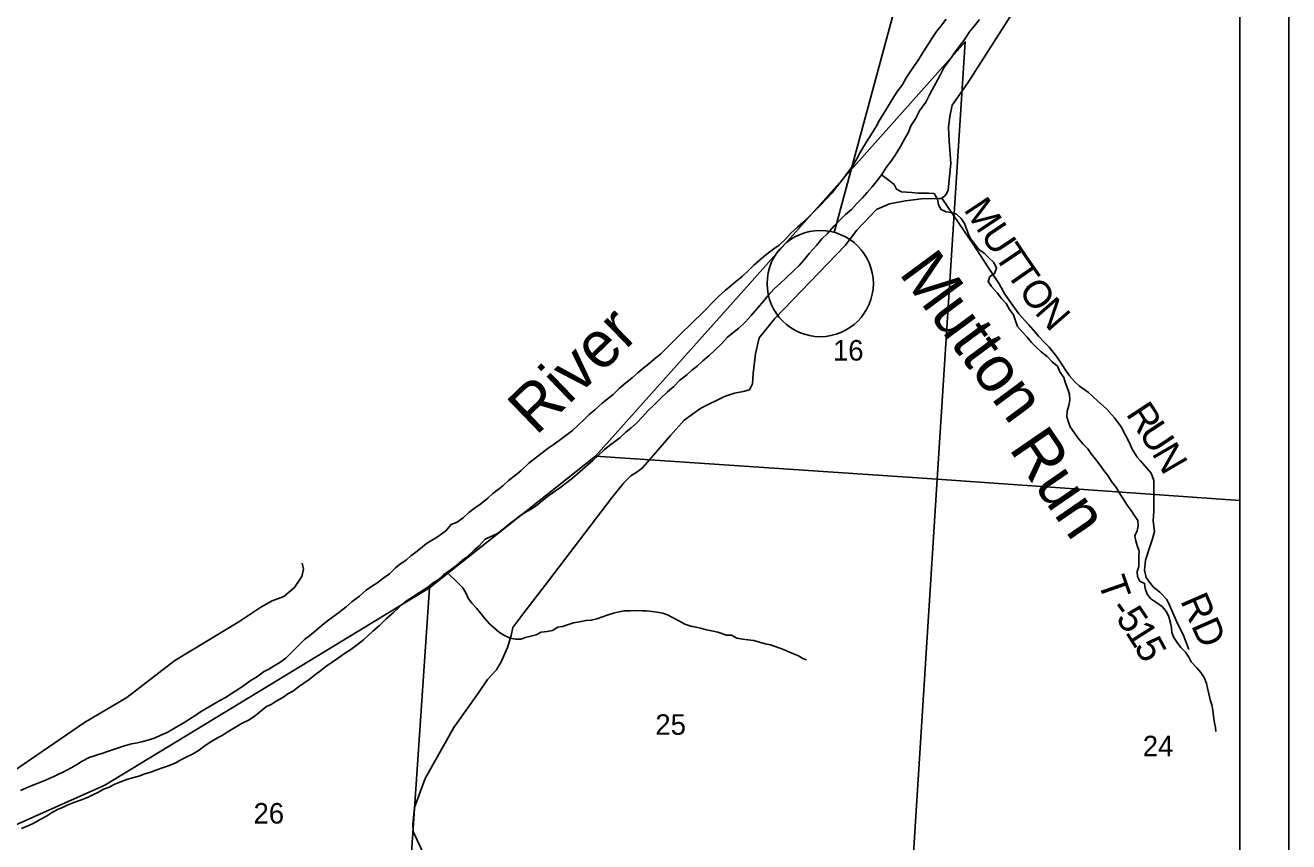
# Model space of a CAD drawing. Extents: x 0 to 34, y 0 to 22.
# Drawn here: x 28.342 to 30.917, y 18.211 to 19.875 of the extents above; entities that cross this region are included whole.
import ezdxf

# ---------------------------------------------------------------- set-up
doc = ezdxf.new("R2010")
doc.units = 0
for name, color, linetype in [('GM_X_County', 7, 'Continuous'), ('GM_X_County_Road', 7, 'Continuous'), ('GM_X_Major_River', 7, 'Continuous'), ('GM_X_Major_River_Text', 7, 'Continuous'), ('GM_X_Minor_River', 7, 'Continuous'), ('GM_X_Minor_River_Text', 7, 'Continuous'), ('GM_X_Section', 7, 'Continuous'), ('GM_X_Section_Text', 7, 'Continuous'), ('GM_X_Township', 7, 'Continuous'), ('GM_X_Township_Road', 7, 'Continuous'), ('GM_X_Township_Road_Text', 7, 'Continuous'), ('SH_Data', 7, 'Continuous'), ('SH_Text', 7, 'Continuous')]:
    doc.layers.add(name, color=color, linetype=linetype)

msp = doc.modelspace()

# ---------------------------------------------------------------- linework, layer by layer
at = {"layer": 'GM_X_County'}
msp.add_lwpolyline([(24.0167, 20.4902), (24.0167, 14.1), (30.8167, 14.1), (30.8167, 19.9966)], dxfattribs=at)
at = {"layer": 'GM_X_County_Road'}
msp.add_lwpolyline([(29.1552, 18.1847), (29.1406, 18.2141), (29.1328, 18.2316), (29.1317, 18.2467), (29.135, 18.2805), (29.1569, 18.3396), (29.2155, 18.444), (29.2659, 18.5147), (29.2838, 18.5419), (29.3021, 18.5615), (29.3121, 18.5778), (29.3244, 18.6066), (29.3321, 18.6316), (29.3356, 18.6479), (29.3562, 18.6747), (29.4085, 18.7427), (29.5364, 18.9113), (29.5616, 18.9422), (29.576, 18.9566), (29.5913, 18.9664), (29.6008, 18.9739), (29.6568, 19.0385), (29.685, 19.0702), (29.7185, 19.0947), (29.7668, 19.1183), (29.7876, 19.125), (29.8051, 19.1287), (29.8176, 19.1317), (29.8241, 19.1442), (29.825, 19.1654), (29.8302, 19.2053), (29.8376, 19.2375), (29.8692, 19.2771), (30.0126, 19.4263), (30.0366, 19.4573), (30.0622, 19.4844), (30.0763, 19.4996), (30.1029, 19.5112), (30.1355, 19.5171), (30.1681, 19.521), (30.2053, 19.5217), (30.2083, 19.5219), (30.2097, 19.5223), (30.2151, 19.5265), (30.2196, 19.5314), (30.2227, 19.5386), (30.2284, 19.594), (30.2245, 19.6384), (30.2235, 19.6661), (30.2259, 19.6885), (30.2306, 19.7117), (30.2627, 19.7574), (30.358, 19.9065)], dxfattribs=at)
at = {"layer": 'GM_X_Major_River'}
for points in [[(30.2186, 19.8869), (30.2075, 19.873), (30.1991, 19.8617), (30.1906, 19.8496), (30.1825, 19.8372), (30.1748, 19.8251), (30.1682, 19.8142), (30.1609, 19.8025), (30.1544, 19.7927), (30.1455, 19.7795), (30.1371, 19.7678), (30.1297, 19.7543), (30.1182, 19.7381), (30.1086, 19.7234), (30.0986, 19.7064), (30.0909, 19.6943), (30.0828, 19.6812), (30.0758, 19.6687), (30.0658, 19.6521), (30.0565, 19.637), (30.05, 19.6269), (30.0442, 19.6171), (30.0373, 19.6042), (30.0288, 19.5899), (30.0219, 19.5798), (30.0138, 19.5685), (30.0061, 19.5583), (29.9938, 19.5432), (29.9862, 19.5335), (29.9739, 19.5203), (29.9632, 19.5087), (29.9509, 19.4963), (29.9394, 19.4854), (29.9268, 19.473), (29.9157, 19.4633), (29.9023, 19.4509), (29.8916, 19.4396), (29.8786, 19.4268), (29.8672, 19.4194), (29.8569, 19.4119), (29.8462, 19.4029), (29.8366, 19.3947), (29.8263, 19.3853), (29.8156, 19.3748), (29.803, 19.3628), (29.7896, 19.3519), (29.7797, 19.3436), (29.7682, 19.3343), (29.7548, 19.3223), (29.7407, 19.308), (29.7318, 19.2982), (29.7181, 19.2847), (29.7058, 19.2731), (29.6947, 19.2626), (29.6836, 19.2517), (29.6637, 19.2314), (29.6496, 19.2172), (29.637, 19.2055), (29.6236, 19.1943), (29.6129, 19.1849), (29.6007, 19.1752), (29.59, 19.1662), (29.5785, 19.1565), (29.5659, 19.146), (29.5525, 19.1347), (29.5399, 19.1223), (29.5304, 19.1149), (29.5174, 19.1044), (29.5028, 19.0912), (29.4914, 19.0815), (29.4811, 19.0717), (29.4681, 19.0594), (29.4573, 19.0492), (29.4436, 19.0388), (29.4299, 19.0286), (29.418, 19.02), (29.4077, 19.0129), (29.3955, 19.0036), (29.3841, 18.995), (29.368, 18.9823), (29.3524, 18.9676), (29.3409, 18.9583), (29.3268, 18.947), (29.3153, 18.9361), (29.3054, 18.929), (29.2947, 18.9204), (29.2844, 18.9114), (29.2706, 18.8998), (29.2592, 18.892)], [(29.3045, 18.8388), (29.319, 18.8508), (29.3297, 18.8598), (29.3396, 18.8673), (29.3499, 18.8751), (29.3652, 18.8849), (29.377, 18.8916), (29.3865, 18.8983), (29.3961, 18.9062), (29.409, 18.9163), (29.4228, 18.926), (29.4331, 18.9338), (29.4453, 18.9432), (29.4571, 18.9522), (29.4671, 18.9604), (29.4774, 18.9694), (29.4881, 18.9792), (29.4984, 18.9882), (29.5095, 18.9983), (29.5217, 19.0099), (29.5324, 19.0185), (29.5427, 19.0256), (29.5534, 19.0343), (29.566, 19.0455), (29.5763, 19.0537), (29.5874, 19.0639), (29.6001, 19.077), (29.6108, 19.089), (29.6226, 19.1007), (29.6356, 19.1138), (29.6509, 19.1281), (29.6636, 19.1389), (29.6762, 19.1517), (29.6903, 19.1622), (29.7006, 19.1719), (29.7109, 19.1798), (29.7228, 19.191), (29.7354, 19.2015), (29.7465, 19.212), (29.7599, 19.2252), (29.7729, 19.2391), (29.784, 19.2477), (29.7962, 19.2578), (29.8088, 19.2698), (29.8211, 19.2833), (29.8341, 19.298), (29.8468, 19.3134), (29.8552, 19.3232), (29.8682, 19.3375), (29.8808, 19.3491), (29.8927, 19.3604), (29.9061, 19.3727), (29.9191, 19.3855), (29.9287, 19.396), (29.9394, 19.4099), (29.9547, 19.4257), (29.9651, 19.4393), (29.977, 19.4505), (29.9904, 19.4663), (30.0015, 19.4768), (30.0133, 19.4888), (30.026, 19.4993), (30.0367, 19.5114), (30.0478, 19.523), (30.0574, 19.5339), (30.0677, 19.5456), (30.0788, 19.5591), (30.0873, 19.5708), (30.0965, 19.5847), (30.1077, 19.6001), (30.115, 19.6103), (30.1258, 19.6276), (30.1347, 19.6442), (30.1416, 19.6571), (30.1467, 19.6695), (30.1559, 19.6842), (30.1644, 19.7001), (30.1771, 19.7178), (30.1848, 19.7332), (30.1902, 19.7434), (30.1976, 19.7566), (30.2061, 19.7732), (30.2138, 19.7879), (30.223, 19.8004), (30.23, 19.8102), (30.2369, 19.8207), (30.245, 19.8312), (30.2569, 19.8463), (30.2657, 19.861), (30.2757, 19.8727), (30.2864, 19.8862)], [(29.2592, 18.892), (29.2462, 18.8819), (29.2343, 18.871), (29.2221, 18.862), (29.2096, 18.8576), (29.1988, 18.8448), (29.1843, 18.834), (29.1733, 18.8269), (29.1596, 18.8187), (29.1477, 18.8089), (29.1382, 18.8014), (29.1279, 18.7939), (29.1179, 18.7846), (29.1073, 18.7779), (29.0966, 18.7689), (29.084, 18.7569), (29.0706, 18.7471), (29.0607, 18.7396), (29.0473, 18.7311), (29.037, 18.7236), (29.0229, 18.7116), (29.0076, 18.6996), (28.9962, 18.6899), (28.9839, 18.6801), (28.9572, 18.6607), (28.9477, 18.6532), (28.9332, 18.6408), (28.9209, 18.6303), (28.911, 18.6229), (28.8965, 18.609), (28.885, 18.597), (28.8728, 18.5853), (28.8606, 18.5764), (28.8495, 18.5696), (28.8381, 18.5629), (28.8278, 18.557), (28.8152, 18.548), (28.8003, 18.5387), (28.7896, 18.5308), (28.7744, 18.5207), (28.7622, 18.5133), (28.7511, 18.5058), (28.7386, 18.4991), (28.7233, 18.4898), (28.7104, 18.4823), (28.6993, 18.4756), (28.6894, 18.4689), (28.6764, 18.461), (28.6635, 18.4525), (28.6463, 18.4428), (28.6311, 18.4338), (28.6182, 18.4279), (28.6068, 18.4231), (28.5946, 18.4186), (28.5817, 18.4154), (28.5707, 18.4128), (28.5585, 18.4103), (28.5441, 18.4063), (28.5338, 18.4029), (28.5198, 18.3985), (28.5099, 18.3952), (28.5004, 18.3915)], [(28.4915, 18.3124), (28.5015, 18.3183), (28.5114, 18.3217), (28.5247, 18.3284), (28.535, 18.3324), (28.5487, 18.3376), (28.5605, 18.3413), (28.5734, 18.3449), (28.5859, 18.3494), (28.5981, 18.3526), (28.6103, 18.3575), (28.6217, 18.3615), (28.6338, 18.3656), (28.6487, 18.3715), (28.6593, 18.3778), (28.6715, 18.3838), (28.6829, 18.3897), (28.6963, 18.3979), (28.7089, 18.4069), (28.7199, 18.4144), (28.7336, 18.4229), (28.7432, 18.4278), (28.7535, 18.4345), (28.7668, 18.4427), (28.7843, 18.4524), (28.7969, 18.4591), (28.8102, 18.4677), (28.8224, 18.4778), (28.8335, 18.4864), (28.843, 18.4905), (28.8533, 18.4972), (28.8667, 18.505), (28.8773, 18.5125), (28.8884, 18.5185), (28.8991, 18.5267), (28.9204, 18.5416), (28.9338, 18.5525), (28.9445, 18.56), (28.9548, 18.5678), (28.9674, 18.5768), (28.9781, 18.5847), (28.9926, 18.5948), (29.0055, 18.603), (29.0193, 18.6131), (29.0311, 18.6224), (29.041, 18.631), (29.0506, 18.6404), (29.064, 18.6517), (29.0777, 18.6652), (29.0922, 18.6779), (29.1049, 18.6895), (29.1144, 18.6986), (29.1255, 18.706), (29.14, 18.7157), (29.1506, 18.7221), (29.1625, 18.7295), (29.1735, 18.7389), (29.1842, 18.7456), (29.1945, 18.7546), (29.2079, 18.7643), (29.2193, 18.773), (29.232, 18.7846), (29.2419, 18.7909), (29.2575, 18.8059), (29.2671, 18.8142), (29.2794, 18.8277), (29.3045, 18.8388)], [(28.5004, 18.3915), (28.4722, 18.3827), (28.4581, 18.3749), (28.4486, 18.3693), (28.4368, 18.3623), (28.4265, 18.3571), (28.3999, 18.3441), (28.3832, 18.3363), (28.3714, 18.3315), (28.3577, 18.326), (28.3433, 18.3201), (28.3326, 18.3157)], [(28.3341, 18.2379), (28.3462, 18.2427), (28.358, 18.2483), (28.3725, 18.2561), (28.3854, 18.2631), (28.3957, 18.2702), (28.4075, 18.2765), (28.4181, 18.2806), (28.4276, 18.2858), (28.4409, 18.2913), (28.4546, 18.2961), (28.4687, 18.3012), (28.4797, 18.3064), (28.4915, 18.3124)]]:
    msp.add_lwpolyline(points, dxfattribs=at)
at = {"layer": 'GM_X_Minor_River'}
for points in [[(30.0867, 19.5699), (30.1024, 19.5581), (30.1125, 19.5503), (30.1172, 19.5407), (30.1277, 19.5355), (30.1379, 19.5345), (30.1489, 19.5343), (30.1613, 19.5329), (30.1715, 19.5323), (30.1825, 19.5328), (30.1939, 19.5322), (30.2012, 19.5202), (30.2032, 19.5088), (30.2083, 19.4992), (30.2184, 19.4944), (30.229, 19.4931), (30.2395, 19.4898), (30.2495, 19.4812), (30.2557, 19.4705), (30.2597, 19.4601), (30.264, 19.4494), (30.269, 19.4391), (30.2768, 19.4287), (30.2852, 19.4175), (30.2957, 19.4104), (30.3053, 19.4007), (30.3157, 19.3914), (30.3211, 19.3795), (30.3174, 19.3686), (30.3078, 19.3627), (30.3042, 19.3526), (30.3108, 19.3422), (30.3226, 19.3294), (30.3311, 19.3182), (30.3411, 19.3077), (30.3476, 19.2958), (30.3557, 19.285), (30.3589, 19.2743), (30.3639, 19.2609), (30.375, 19.2489), (30.3838, 19.2393), (30.3927, 19.2281), (30.4023, 19.2191), (30.4119, 19.2094), (30.4242, 19.2), (30.4346, 19.1892), (30.4457, 19.1798), (30.4504, 19.1687), (30.4585, 19.1568), (30.4616, 19.1454), (30.4667, 19.1331), (30.4702, 19.1228), (30.4703, 19.1106), (30.4689, 19.0997), (30.4653, 19.0884), (30.4646, 19.0766), (30.4678, 19.0663), (30.4714, 19.0564), (30.4794, 19.0452), (30.4871, 19.034), (30.4975, 19.0213), (30.5071, 19.0116), (30.5144, 19.0016), (30.5229, 18.9907), (30.5317, 18.9792), (30.5398, 18.9672), (30.5479, 18.9572), (30.5556, 18.9453), (30.5659, 18.9321), (30.5721, 18.921), (30.5794, 18.9098), (30.5875, 18.8971), (30.5959, 18.886), (30.6018, 18.8763), (30.6095, 18.8655), (30.61, 18.8545), (30.6075, 18.8443), (30.6031, 18.8342), (30.6048, 18.8243), (30.6076, 18.8144), (30.6122, 18.8033), (30.6113, 18.7931), (30.611, 18.7828), (30.6112, 18.7718), (30.6079, 18.7616), (30.6084, 18.7518), (30.6131, 18.7422), (30.6229, 18.7374), (30.6242, 18.7271), (30.6281, 18.7157), (30.6358, 18.706), (30.6459, 18.6994), (30.6597, 18.6896), (30.6674, 18.6792), (30.6725, 18.6696), (30.676, 18.657), (30.6777, 18.6467), (30.6786, 18.6372), (30.6825, 18.6269), (30.6891, 18.6168), (30.6965, 18.6068)], [(29.2019, 18.7599), (29.2231, 18.7393), (29.2338, 18.7284), (29.2397, 18.7184), (29.2447, 18.7073), (29.2521, 18.6969), (29.2613, 18.6868), (29.2705, 18.6764), (29.2783, 18.6656), (29.2883, 18.6551), (29.2979, 18.6462), (29.3087, 18.6372), (29.3184, 18.6313), (29.33, 18.6258), (29.3413, 18.6236), (29.3519, 18.6241), (29.3615, 18.627), (29.3721, 18.6298), (29.3828, 18.6329), (29.3932, 18.638), (29.4053, 18.6393), (29.4163, 18.6417), (29.4271, 18.6483), (29.4366, 18.6499), (29.4469, 18.6531), (29.4591, 18.657), (29.4717, 18.6594), (29.485, 18.6621), (29.4952, 18.6623), (29.5066, 18.6655), (29.5185, 18.669), (29.5295, 18.6733), (29.541, 18.6768), (29.552, 18.6792), (29.5627, 18.6813), (29.574, 18.6818), (29.585, 18.6819), (29.5987, 18.6816), (29.6081, 18.6818), (29.6194, 18.68), (29.6296, 18.679), (29.641, 18.6765), (29.6507, 18.6733), (29.6612, 18.6681), (29.6754, 18.6602), (29.6863, 18.6546), (29.6983, 18.6506), (29.7089, 18.6481), (29.7206, 18.6455), (29.7303, 18.6427), (29.7405, 18.6405), (29.753, 18.638), (29.771, 18.6319), (29.7812, 18.6321), (29.7921, 18.6261), (29.8045, 18.6236), (29.8147, 18.6222), (29.8264, 18.6208), (29.8385, 18.6175), (29.8498, 18.6146), (29.8603, 18.6121), (29.8701, 18.6092), (29.8817, 18.6048), (29.8922, 18.6008), (29.9039, 18.5952), (29.9163, 18.5907), (29.9263, 18.5841), (29.9339, 18.5816)], [(30.6965, 18.6068), (30.7061, 18.5975), (30.7134, 18.5871), (30.7181, 18.5775), (30.7285, 18.5663), (30.7377, 18.5558), (30.7443, 18.5455), (30.749, 18.5332), (30.751, 18.5237), (30.7538, 18.5126), (30.7569, 18.5), (30.7597, 18.4901), (30.7618, 18.4791), (30.7634, 18.4669), (30.7653, 18.4532), (30.7674, 18.4437), (30.7684, 18.4357)]]:
    msp.add_lwpolyline(points, dxfattribs=at)
at = {"layer": 'GM_X_Section'}
msp.add_line((30.8167, 17.9065), (30.8167, 18.9061), dxfattribs=at)
for points in [[(29.7952, 19.323), (30.2571, 19.8411), (30.2006, 18.9496), (29.5042, 18.9967)], [(29.5042, 18.9967), (30.2006, 18.9496), (30.1374, 17.9516), (29.1178, 18.0184), (29.1658, 18.7281)], [(29.1658, 18.7281), (29.1178, 18.0184), (28.5033, 18.0906), (28.5064, 18.0521), (28.157, 18.0791), (28.1647, 18.1688), (28.1804, 18.1807), (28.214, 18.1975), (28.5041, 18.3264), (28.8554, 18.5398)]]:
    msp.add_lwpolyline(points, close=True, dxfattribs=at)
msp.add_lwpolyline([(30.8167, 18.9061), (30.2006, 18.9496), (30.1374, 17.9516), (30.8167, 17.9065)], dxfattribs=at)
at = {"layer": 'GM_X_Township'}
msp.add_lwpolyline([(27.704, 14.1), (30.8167, 14.1), (30.8167, 19.9966)], dxfattribs=at)
at = {"layer": 'GM_X_Township_Road'}
for points in [[(30.7133, 18.6028), (30.7013, 18.6332), (30.6897, 18.6557), (30.6826, 18.6724), (30.6737, 18.693), (30.6681, 18.7047), (30.6538, 18.7193), (30.6402, 18.7303), (30.6349, 18.7372), (30.6259, 18.7494), (30.6226, 18.7642), (30.6246, 18.7851), (30.6327, 18.8101), (30.6389, 18.8283), (30.6431, 18.8431), (30.6402, 18.8658), (30.6419, 18.8848), (30.642, 18.9061), (30.6417, 18.9205), (30.6418, 18.9345), (30.6419, 18.9474), (30.6363, 18.9619), (30.6148, 18.9875), (30.6081, 18.9947), (30.5975, 19.0107), (30.5919, 19.0236), (30.5751, 19.0564), (30.5616, 19.0747), (30.5458, 19.0926), (30.5269, 19.1094), (30.5085, 19.1266), (30.4904, 19.1396), (30.4809, 19.1484), (30.4697, 19.1606), (30.4614, 19.1736), (30.4516, 19.188), (30.4423, 19.2021), (30.4287, 19.2185), (30.4193, 19.2285), (30.4065, 19.2411), (30.396, 19.254), (30.3866, 19.2651), (30.367, 19.2865), (30.3509, 19.3086), (30.3381, 19.3265), (30.3265, 19.3482), (30.3032, 19.3825), (30.2736, 19.4286), (30.2341, 19.4865), (30.2097, 19.5223)], [(27.1485, 18.1572), (27.153, 18.1629), (27.1629, 18.1674), (27.1753, 18.1651), (27.1953, 18.1509), (27.2498, 18.1328), (27.436, 18.1203), (27.6307, 18.1188), (27.944, 18.1227), (27.9625, 18.1237), (27.9982, 18.1364), (28.4629, 18.4537), (28.5488, 18.5052), (28.6466, 18.5805), (28.777, 18.6591), (28.8222, 18.6888), (28.8454, 18.7016), (28.8686, 18.7105), (28.8906, 18.7294), (28.9056, 18.7513), (28.9087, 18.7665), (28.9065, 18.7786)]]:
    msp.add_lwpolyline(points, dxfattribs=at)
at = {"layer": 'SH_Data'}
for points in [[(23.9167, 21), (30.9167, 21), (30.9167, 14), (23.9167, 14)], [(24.0167, 20.9), (30.8167, 20.9), (30.8167, 14.1), (24.0167, 14.1)]]:
    msp.add_lwpolyline(points, close=True, dxfattribs=at)
at = {"layer": 'SH_Text'}
msp.add_line((29.9902, 19.4527), (30.4732, 21.2354), dxfattribs=at)
msp.add_circle((29.962, 19.3483), 0.1082, dxfattribs=at)

# ---------------------------------------------------------------- texts
at = {"layer": 'GM_X_Major_River_Text'}
msp.add_text('River', height=0.09471, rotation=43.9767, dxfattribs=at).set_placement((29.3829, 19.037))
at = {"layer": 'GM_X_Minor_River_Text'}
for s, height, rotation, p in [('Mutton', 0.0947, 306.477, (30.121, 19.3693)), ('Run', 0.09471, 304.4804, (30.3451, 19.0121))]:
    msp.add_text(s, height=height, rotation=rotation, dxfattribs=at).set_placement(p)
at = {"layer": 'GM_X_Section_Text'}
for s, p in [('16', (29.988, 19.1915)), ('25', (29.626, 18.429)), ('24', (30.6193, 18.3851)), ('26', (28.8072, 18.2481))]:
    msp.add_text(s, height=0.04186, rotation=0, dxfattribs=at).set_placement(p)
at = {"layer": 'GM_X_Township_Road_Text'}
for s, height, rotation, p in [('M', 0.0568, 303.5328, (30.2531, 19.4992)), ('U', 0.0568, 303.5372, (30.2872, 19.4478)), ('T', 0.0568, 303.8085, (30.315, 19.4058)), ('T', 0.0568, 304.9313, (30.3393, 19.3695)), ('O', 0.0568, 306.0268, (30.3643, 19.3337)), ('N', 0.0568, 311.1718, (30.3972, 19.2889)), ('R', 0.0568, 303.3848, (30.5838, 19.0827)), ('U', 0.0568, 303.3466, (30.6095, 19.0437)), ('N', 0.0568, 300.1841, (30.6365, 19.0026)), ('T', 0.0568, 289.1871, (30.5272, 18.7411)), ('RD', 0.05682, 293.7139, (30.6951, 18.7022)), ('-', 0.0568, 305.9646, (30.5496, 18.6849)), ('5', 0.0568, 304.2212, (30.563, 18.6664)), ('1', 0.0568, 302.4025, (30.5824, 18.6379)), ('5', 0.0568, 298.2292, (30.6006, 18.6093))]:
    msp.add_text(s, height=height, rotation=rotation, dxfattribs=at).set_placement(p)

doc.saveas('drawing.dxf')
